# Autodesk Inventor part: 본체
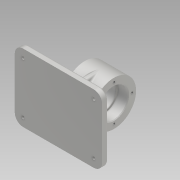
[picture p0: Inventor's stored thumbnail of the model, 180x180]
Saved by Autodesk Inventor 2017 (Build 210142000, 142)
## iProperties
Part Number: 본체
Material: 알루미늄 6061
Document SubType Name: Modeling
Designer: 603-17
Density: 2.7 g/cm^3
Appearance: 알루미늄 - 평지
Mass: 554.361 g
Surface Area: 496.445 cm^2
Volume: 205.319 cm^3
Author: 603-17
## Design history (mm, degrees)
sketch "스케치1"
  geometry: L1 (63, 49)-(-63, 49); L2 (-63, 49)-(-63, -49); L3 (-63, -49)-(63, -49); L4 (63, -49)-(63, 49); L5 (63, 49)-(-63, -49); L6 (-63, 49)-(63, -49); 1 further point
  constraints: 12 end point, 2 midpoint, 2 parallel, 1 horizontal, 1 perpendicular
  dimensions: "d0" = 126 distance of L2.end L3.end; "d1" = 98 distance of L1.end L2.end
extrude "돌출1" new body sketch "스케치1" distance "d2" = 9; taper "d3" = 0 deg
node "작업 평면1"
sketch "스케치2"
  geometry: L1 (0, 49)-(9, 49) reference; L2 (9, 49)-(9, -49) reference; L3 (9, -49)-(0, -49) reference; L4 (0, -49)-(0, 49) reference; L5 (0, 49)-(0, -13); L6 (0, -13)-(59, -13); C1 r 32 at (59, -13); 1 further point
  constraints: 4 end point, 1 centre point, 1 coincident, 1 horizontal, 1 vertical
  dimensions: "d5" = 62 distance of L1.start L5.end; "d6" = 59 distance of L5.end L6.end; "d7" = 64 diameter of C1
extrude "돌출2" join sketch "스케치2" stored distance "d8" = 42; taper "d9" = 0 deg
sketch "스케치3"
  geometry: L1 (0, 49)-(9, 49) reference; L2 (9, 49)-(9, -49) reference; L3 (9, -49)-(0, -49) reference; L4 (0, -49)-(0, 49) reference; L5 (59, -45)-(4.5, -45); L6 (59, 19)-(4.5, 19); L7 (4.5, -45)-(4.5, 19); A1 r 32 centre (59, -13) between (59, -45) and (59, 19) reference; 1 further point
  constraints: 6 end point, 2 point on circle, 1 horizontal, 1 parallel, 1 perpendicular, 1 tangent
extrude "돌출3" join sketch "스케치3" stored distance "d10" = 8; taper "d11" = 0 deg
node "작업 평면2"
sketch "스케치4"
  geometry: L1 (126, 9)-(126, 0) reference; L2 (126, 0)-(0, 0) reference; L3 (0, 0)-(0, 9) reference; L4 (0, 9)-(59, 9) reference; L5 (59, 9)-(59, 27) reference; L6 (59, 27)-(42, 27) reference; L7 (42, 27)-(42, 91) reference; L8 (42, 91)-(84, 91) reference; L9 (84, 91)-(84, 27) reference; L10 (84, 27)-(67, 27) reference; L11 (67, 27)-(67, 9) reference; L12 (67, 9)-(126, 9) reference; L13 (46, 0)-(80, 0); L14 (80, 0)-(80, 42.607); L15 (80, 42.607)-(46, 42.607); L16 (46, 42.607)-(46, 0); 3 further points
  constraints: 8 end point, 2 coincident, 2 midpoint, 2 parallel, 1 horizontal, 1 perpendicular
  dimensions: "d13" = 34 distance of L14.end L15.end
extrude "돌출4" join sketch "스케치4" stored distance "d14" = 8; taper "d15" = 0 deg
fillet "모깎기1" dims "d16" = 12
fillet "모깎기2" dims "d17" = 3
fillet "모깎기3" dims "d18" = 3
fillet "모깎기4" dims "d19" = 3
fillet "모깎기5" dims "d20" = 3
fillet "모깎기6" dims "d21" = 3
sketch "스케치5"
  geometry: L1 (-59, -50)-(33, -50) reference; L2 (36, -53)-(36, -59) reference; L3 (36, -59)-(-62, -59) reference; L4 (-62, -59)-(-62, -53) reference; C1 r 32 at (0, 0) reference; C2 r 18 at (0, 0); A1 r 3 centre (-59, -53) between (-59, -50) and (-62, -53) reference; A2 r 3 centre (33, -53) between (36, -53) and (33, -50) reference; 1 further point
  constraints: 1 centre point, 1 coincident
  dimensions: "d22" = 36 diameter of C2
extrude "돌출5" cut sketch "스케치5" stored distance "d23" = 8; taper "d24" = 0 deg
sketch "스케치6"
  geometry: C1 r 21 at (0, 0); 1 further point
  constraints: 1 centre point
  dimensions: "d25" = 42 diameter of C1
extrude "돌출6" cut sketch "스케치6" distance "d26" = 15; taper "d27" = 0 deg
fillet "모깎기7" dims "d28" = 0.3
chamfer "모따기1" distance "d29" = 1; stored, may be unused: second distance "d30" = 2, angle "d31" = 45 deg
sketch "스케치7" dims "d32" = 52
  geometry: L1 (-59, -50)-(33, -50) reference; L2 (36, -53)-(36, -59) reference; L3 (36, -59)-(-62, -59) reference; L4 (-62, -59)-(-62, -53) reference; L5 (0, 0)-(0, 26); C1 r 22 at (0, 0) reference; C2 r 32 at (0, 0) reference; A1 r 3 centre (-59, -53) between (-59, -50) and (-62, -53) reference; A2 r 3 centre (33, -53) between (36, -53) and (33, -50) reference; 1 further point
  constraints: 2 end point, 1 coincident, 1 vertical, 1 vertical alignment, 2 other
hole "구멍1" sketch "스케치7" at (0, 26) diameter "d33" = 3.459; stored, may be unused: countersink angle "d37" = 90 deg, drill point angle "d39" = 118 deg; dims "d34" = 8, "d35" = 4, "d36" = 2, "d38" = 10
sketch "스케치8"
  geometry: L1 (60, -37)-(60, 37) reference; L2 (51, 46)-(5.472, 46) reference; L3 (-1, 46.607)-(1, 46.607) reference; L4 (-5.472, 46)-(-51, 46) reference; L5 (-60, 37)-(-60, -37) reference; L6 (-51, -46)-(51, -46) reference; L7 (7, 20)-(7, 42) reference; L8 (14, 20)-(7, 20) reference; L9 (20, 12)-(20, 14) reference; L10 (7, 6)-(14, 6) reference; L11 (7, -16)-(7, 6) reference; L12 (-1, -22)-(1, -22) reference; L13 (-7, 6)-(-7, -16) reference; L14 (-14, 6)-(-7, 6) reference; L15 (-20, 14)-(-20, 12) reference; L16 (-7, 20)-(-14, 20) reference; L17 (-7, 42)-(-7, 20) reference; C1 r 2.25 at (51, 37); C2 r 2.25 at (-51, 37); C3 r 2.25 at (-51, -37); C4 r 2.25 at (51, -37); A1 r 9 centre (51, -37) between (51, -46) and (60, -37) reference; A2 r 9 centre (51, 37) between (60, 37) and (51, 46) reference; A3 r 9 centre (-51, 37) between (-51, 46) and (-60, 37) reference; A4 r 9 centre (-51, -37) between (-60, -37) and (-51, -46) reference; A5 r 6 centre (1, 42) between (7, 42) and (5.472, 46) reference; A6 r 6 centre (14, 14) between (20, 14) and (14, 20) reference; A7 r 6 centre (14, 12) between (14, 6) and (20, 12) reference; A8 r 6 centre (1, -16) between (1, -22) and (7, -16) reference; A9 r 6 centre (-1, -16) between (-7, -16) and (-1, -22) reference; A10 r 6 centre (-14, 12) between (-20, 12) and (-14, 6) reference; A11 r 6 centre (-14, 14) between (-14, 20) and (-20, 14) reference; A12 r 6 centre (-1, 42) between (-5.472, 46) and (-7, 42) reference; 1 further point
  constraints: 4 centre point, 4 coincident, 2 other
  dimensions: "d43" = 4.5 diameter of C2; "d44" = 4.5 diameter of C1; "d45" = 4.5 diameter of C3; "d46" = 4.5 diameter of C4
extrude "돌출7" cut sketch "스케치8" stored distance "d47" = 15; taper "d48" = 0 deg
sketch "스케치9"
  geometry: L1 (60, -37)-(60, 37) reference; L2 (51, 46)-(5.472, 46) reference; L3 (-1, 46.607)-(1, 46.607) reference; L4 (-5.472, 46)-(-51, 46) reference; L5 (-60, 37)-(-60, -37) reference; L6 (-51, -46)-(51, -46) reference; L7 (7, 20)-(7, 42) reference; L8 (14, 20)-(7, 20) reference; L9 (20, 12)-(20, 14) reference; L10 (7, 6)-(14, 6) reference; L11 (7, -16)-(7, 6) reference; L12 (-1, -22)-(1, -22) reference; L13 (-7, 6)-(-7, -16) reference; L14 (-14, 6)-(-7, 6) reference; L15 (-20, 14)-(-20, 12) reference; L16 (-7, 20)-(-14, 20) reference; L17 (-7, 42)-(-7, 20) reference; C1 r 2.25 at (-51, -37) reference; C2 r 2.25 at (51, 37) reference; C3 r 2.25 at (-51, 37) reference; C4 r 2.25 at (51, -37) reference; C5 r 4 at (-51, 37); C6 r 4 at (51, 37); C7 r 4 at (51, -37); C8 r 4 at (-51, -37); A1 r 9 centre (51, -37) between (51, -46) and (60, -37) reference; A2 r 9 centre (51, 37) between (60, 37) and (51, 46) reference; A3 r 9 centre (-51, 37) between (-51, 46) and (-60, 37) reference; A4 r 9 centre (-51, -37) between (-60, -37) and (-51, -46) reference; A5 r 6 centre (1, 42) between (7, 42) and (5.472, 46) reference; A6 r 6 centre (14, 14) between (20, 14) and (14, 20) reference; A7 r 6 centre (14, 12) between (14, 6) and (20, 12) reference; A8 r 6 centre (1, -16) between (1, -22) and (7, -16) reference; A9 r 6 centre (-1, -16) between (-7, -16) and (-1, -22) reference; A10 r 6 centre (-14, 12) between (-20, 12) and (-14, 6) reference; A11 r 6 centre (-14, 14) between (-14, 20) and (-20, 14) reference; A12 r 6 centre (-1, 42) between (-5.472, 46) and (-7, 42) reference; 1 further point
  constraints: 4 centre point, 4 coincident, 2 other
  dimensions: "d49" = 8 diameter of C5; "d50" = 8 diameter of C6; "d51" = 8 diameter of C7; "d52" = 8 diameter of C8
extrude "돌출8" cut sketch "스케치9" distance "d53" = 4.4; taper "d54" = 0 deg
sketch "스케치11"
  geometry: L1 (60, -37)-(60, 37) reference; L2 (51, 46)-(5.472, 46) reference; L3 (-1, 46.607)-(1, 46.607) reference; L4 (-5.472, 46)-(-51, 46) reference; L5 (-60, 37)-(-60, -37) reference; L6 (-51, -46)-(51, -46) reference; L7 (7, 20)-(7, 42) reference; L8 (14, 20)-(7, 20) reference; L9 (20, 12)-(20, 14) reference; L10 (7, 6)-(14, 6) reference; L11 (7, -16)-(7, 6) reference; L12 (-1, -22)-(1, -22) reference; L13 (-7, 6)-(-7, -16) reference; L14 (-14, 6)-(-7, 6) reference; L15 (-20, 14)-(-20, 12) reference; L16 (-7, 20)-(-14, 20) reference; L17 (-7, 42)-(-7, 20) reference; L18 (29.03, -19.34)-(-29.03, -19.34); L19 (-29.03, -19.34)-(-29.03, -58.66); L20 (-29.03, -58.66)-(29.03, -58.66); L21 (29.03, -58.66)-(29.03, -19.34); L22 (-51, -49)-(51, -49) reference; C1 r 4 at (51, -37) reference; C2 r 4 at (-51, 37) reference; C3 r 4 at (51, 37) reference; C4 r 4 at (-51, -37) reference; A1 r 9 centre (51, -37) between (51, -46) and (60, -37) reference; A2 r 9 centre (51, 37) between (60, 37) and (51, 46) reference; A3 r 9 centre (-51, 37) between (-51, 46) and (-60, 37) reference; A4 r 9 centre (-51, -37) between (-60, -37) and (-51, -46) reference; A5 r 6 centre (1, 42) between (7, 42) and (5.472, 46) reference; A6 r 6 centre (14, 14) between (20, 14) and (14, 20) reference; A7 r 6 centre (14, 12) between (14, 6) and (20, 12) reference; A8 r 6 centre (1, -16) between (1, -22) and (7, -16) reference; A9 r 6 centre (-1, -16) between (-7, -16) and (-1, -22) reference; A10 r 6 centre (-14, 12) between (-20, 12) and (-14, 6) reference; A11 r 6 centre (-14, 14) between (-14, 20) and (-20, 14) reference; A12 r 6 centre (-1, 42) between (-5.472, 46) and (-7, 42) reference; 5 further points
  constraints: 2 midpoint, 4 other
  dimensions: "d55" = 3 distance between parallel lines of L22 L6 (derived)
feature "엠보싱1" sketch "스케치11" dims "d0" = 126, "d1" = 98, "d58" = 0.5, "d59" = 0
node "솔리드1"
mirror "미러1"
pattern_circular "원형 패턴1" dims angle "d41" = 360 deg
mirror "미러2"
node "절단 모서리 투영1"
node "절단 모서리 투영2"
node "절단 모서리 투영3"
node "절단 모서리 투영4"
node "절단 모서리 투영5"
node "절단 모서리 투영6"
node "절단 모서리 투영7"
node "절단 모서리 투영9"
other parameters: "d4" = 0, "d12" = -62
